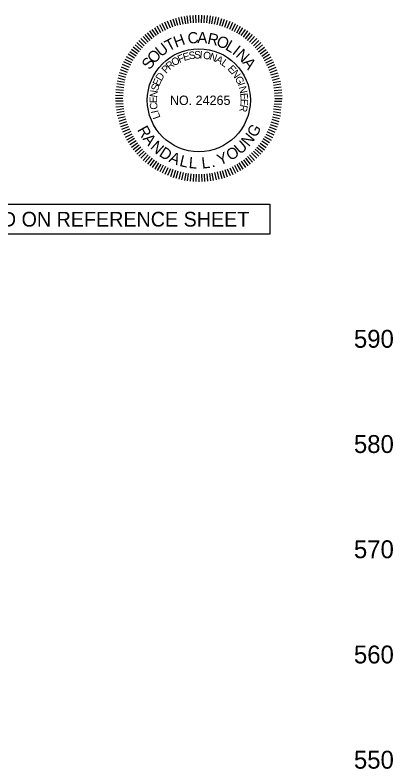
# Model space of a CAD drawing. Extents: x 1964849 to 1967422, y 1116563 to 1122211.
# Drawn here: x 1967242.5 to 1967421.9, y 1119125.5 to 1119483.7 of the extents above; entities that cross this region are included whole.
import ezdxf

# ---------------------------------------------------------------- set-up
doc = ezdxf.new("R2010")
doc.units = 0
for name, color, linetype in [('RD_DDB_Profile_Elev', 7, 'Continuous'), ('RD_Sketch1', 7, 'Continuous'), ('RD_TX_PEShield', 7, 'Continuous')]:
    doc.layers.add(name, color=color, linetype=linetype)

msp = doc.modelspace()

# ---------------------------------------------------------------- linework, layer by layer
at = {"layer": 'RD_Sketch1'}
msp.add_lwpolyline([(1967062.99, 1119393.87), (1967363.41, 1119393.87), (1967363.41, 1119379.61), (1967062.99, 1119379.61)], close=True, dxfattribs=at)
at = {"layer": 'RD_TX_PEShield'}
for p, q in [((1967316.27, 1119477.43), (1967314.93, 1119480.72)), ((1967316.27, 1119477.43), (1967314.93, 1119480.72)), ((1967317.44, 1119477.88), (1967316.22, 1119481.22)), ((1967317.44, 1119477.88), (1967316.22, 1119481.22)), ((1967318.61, 1119478.33), (1967317.51, 1119481.71)), ((1967318.61, 1119478.33), (1967317.51, 1119481.71)), ((1967319.83, 1119478.65), (1967318.85, 1119482.07)), ((1967319.83, 1119478.65), (1967318.85, 1119482.07)), ((1967321.04, 1119478.98), (1967320.18, 1119482.43)), ((1967321.04, 1119478.98), (1967320.18, 1119482.43)), ((1967322.26, 1119479.3), (1967321.52, 1119482.79)), ((1967322.26, 1119479.3), (1967321.52, 1119482.79)), ((1967323.5, 1119479.5), (1967322.88, 1119483)), ((1967323.5, 1119479.5), (1967322.88, 1119483)), ((1967324.74, 1119479.7), (1967324.25, 1119483.22)), ((1967324.74, 1119479.7), (1967324.25, 1119483.22)), ((1967325.98, 1119479.89), (1967325.61, 1119483.43)), ((1967325.98, 1119479.89), (1967325.61, 1119483.43)), ((1967327.24, 1119479.96), (1967326.99, 1119483.51)), ((1967327.24, 1119479.96), (1967326.99, 1119483.51)), ((1967328.5, 1119480.02), (1967328.37, 1119483.58)), ((1967328.5, 1119480.02), (1967328.37, 1119483.58)), ((1967329.75, 1119480.09), (1967329.75, 1119483.65)), ((1967329.75, 1119480.09), (1967329.75, 1119483.65)), ((1967331.01, 1119480.02), (1967331.13, 1119483.58)), ((1967331.01, 1119480.02), (1967331.13, 1119483.58)), ((1967332.26, 1119479.96), (1967332.51, 1119483.51)), ((1967332.26, 1119479.96), (1967332.51, 1119483.51)), ((1967333.52, 1119479.89), (1967333.89, 1119483.43)), ((1967333.52, 1119479.89), (1967333.89, 1119483.43)), ((1967334.76, 1119479.7), (1967335.26, 1119483.22)), ((1967334.76, 1119479.7), (1967335.26, 1119483.22)), ((1967336, 1119479.5), (1967336.62, 1119483)), ((1967336, 1119479.5), (1967336.62, 1119483)), ((1967337.25, 1119479.3), (1967337.99, 1119482.79)), ((1967337.25, 1119479.3), (1967337.99, 1119482.79)), ((1967337.25, 1119479.3), (1967337.99, 1119482.79)), ((1967338.46, 1119478.98), (1967339.32, 1119482.43)), ((1967338.46, 1119478.98), (1967339.32, 1119482.43)), ((1967338.46, 1119478.98), (1967339.32, 1119482.43)), ((1967339.68, 1119478.65), (1967340.66, 1119482.07)), ((1967339.68, 1119478.65), (1967340.66, 1119482.07)), ((1967339.68, 1119478.65), (1967340.66, 1119482.07)), ((1967340.89, 1119478.33), (1967341.99, 1119481.71)), ((1967340.89, 1119478.33), (1967341.99, 1119481.71)), ((1967340.89, 1119478.33), (1967341.99, 1119481.71)), ((1967342.07, 1119477.88), (1967343.28, 1119481.22)), ((1967342.07, 1119477.88), (1967343.28, 1119481.22)), ((1967342.07, 1119477.88), (1967343.28, 1119481.22)), ((1967343.24, 1119477.43), (1967344.57, 1119480.72)), ((1967343.24, 1119477.43), (1967344.57, 1119480.72)), ((1967343.24, 1119477.43), (1967344.57, 1119480.72)), ((1967310.67, 1119474.58), (1967308.79, 1119477.59)), ((1967310.67, 1119474.58), (1967308.79, 1119477.59)), ((1967311.73, 1119475.26), (1967309.95, 1119478.34)), ((1967311.73, 1119475.26), (1967309.95, 1119478.34)), ((1967312.85, 1119475.83), (1967311.18, 1119478.97)), ((1967312.85, 1119475.83), (1967311.18, 1119478.97)), ((1967313.97, 1119476.4), (1967312.41, 1119479.6)), ((1967313.97, 1119476.4), (1967312.41, 1119479.6)), ((1967315.09, 1119476.97), (1967313.64, 1119480.23)), ((1967315.09, 1119476.97), (1967313.64, 1119480.23)), ((1967344.41, 1119476.97), (1967345.86, 1119480.23)), ((1967344.41, 1119476.97), (1967345.86, 1119480.23)), ((1967344.41, 1119476.97), (1967345.86, 1119480.23)), ((1967345.53, 1119476.4), (1967347.09, 1119479.6)), ((1967345.53, 1119476.4), (1967347.09, 1119479.6)), ((1967345.53, 1119476.4), (1967347.09, 1119479.6)), ((1967346.65, 1119475.83), (1967348.32, 1119478.97)), ((1967346.65, 1119475.83), (1967348.32, 1119478.97)), ((1967346.65, 1119475.83), (1967348.32, 1119478.97)), ((1967347.78, 1119475.26), (1967349.56, 1119478.34)), ((1967347.78, 1119475.26), (1967349.56, 1119478.34)), ((1967347.78, 1119475.26), (1967349.56, 1119478.34)), ((1967348.83, 1119474.58), (1967350.71, 1119477.59)), ((1967348.83, 1119474.58), (1967350.71, 1119477.59)), ((1967348.83, 1119474.58), (1967350.71, 1119477.59)), ((1967305.63, 1119470.83), (1967303.25, 1119473.48)), ((1967305.63, 1119470.83), (1967303.25, 1119473.48)), ((1967306.61, 1119471.62), (1967304.33, 1119474.35)), ((1967306.61, 1119471.62), (1967304.33, 1119474.35)), ((1967307.59, 1119472.41), (1967305.4, 1119475.22)), ((1967307.59, 1119472.41), (1967305.4, 1119475.22)), ((1967308.57, 1119473.21), (1967306.47, 1119476.09)), ((1967308.57, 1119473.21), (1967306.47, 1119476.09)), ((1967309.62, 1119473.89), (1967307.63, 1119476.84)), ((1967309.62, 1119473.89), (1967307.63, 1119476.84)), ((1967349.88, 1119473.89), (1967351.87, 1119476.84)), ((1967349.88, 1119473.89), (1967351.87, 1119476.84)), ((1967349.88, 1119473.89), (1967351.87, 1119476.84)), ((1967350.94, 1119473.21), (1967353.03, 1119476.09)), ((1967350.94, 1119473.21), (1967353.03, 1119476.09)), ((1967350.94, 1119473.21), (1967353.03, 1119476.09)), ((1967351.92, 1119472.41), (1967354.11, 1119475.22)), ((1967351.92, 1119472.41), (1967354.11, 1119475.22)), ((1967351.92, 1119472.41), (1967354.11, 1119475.22)), ((1967352.89, 1119471.62), (1967355.18, 1119474.35)), ((1967352.89, 1119471.62), (1967355.18, 1119474.35)), ((1967352.89, 1119471.62), (1967355.18, 1119474.35)), ((1967353.87, 1119470.83), (1967356.25, 1119473.48)), ((1967353.87, 1119470.83), (1967356.25, 1119473.48)), ((1967353.87, 1119470.83), (1967356.25, 1119473.48)), ((1967302.97, 1119468.16), (1967300.32, 1119470.55)), ((1967302.97, 1119468.16), (1967300.32, 1119470.55)), ((1967303.86, 1119469.05), (1967301.3, 1119471.52)), ((1967303.86, 1119469.05), (1967301.3, 1119471.52)), ((1967304.74, 1119469.94), (1967302.27, 1119472.5)), ((1967304.74, 1119469.94), (1967302.27, 1119472.5)), ((1967354.76, 1119469.94), (1967357.23, 1119472.5)), ((1967354.76, 1119469.94), (1967357.23, 1119472.5)), ((1967354.76, 1119469.94), (1967357.23, 1119472.5)), ((1967355.65, 1119469.05), (1967358.21, 1119471.52)), ((1967355.65, 1119469.05), (1967358.21, 1119471.52)), ((1967355.65, 1119469.05), (1967358.21, 1119471.52)), ((1967356.54, 1119468.16), (1967359.18, 1119470.55)), ((1967356.54, 1119468.16), (1967359.18, 1119470.55)), ((1967356.54, 1119468.16), (1967359.18, 1119470.55)), ((1967299.91, 1119464.18), (1967296.96, 1119466.17)), ((1967299.91, 1119464.18), (1967296.96, 1119466.17)), ((1967300.59, 1119465.23), (1967297.71, 1119467.32)), ((1967300.59, 1119465.23), (1967297.71, 1119467.32)), ((1967301.38, 1119466.21), (1967298.58, 1119468.4)), ((1967301.38, 1119466.21), (1967298.58, 1119468.4)), ((1967302.17, 1119467.19), (1967299.45, 1119469.47)), ((1967302.17, 1119467.19), (1967299.45, 1119469.47)), ((1967357.33, 1119467.19), (1967360.05, 1119469.47)), ((1967357.33, 1119467.19), (1967360.05, 1119469.47)), ((1967357.33, 1119467.19), (1967360.05, 1119469.47)), ((1967358.12, 1119466.21), (1967360.92, 1119468.4)), ((1967358.12, 1119466.21), (1967360.92, 1119468.4)), ((1967358.12, 1119466.21), (1967360.92, 1119468.4)), ((1967358.91, 1119465.23), (1967361.79, 1119467.32)), ((1967358.91, 1119465.23), (1967361.79, 1119467.32)), ((1967358.91, 1119465.23), (1967361.79, 1119467.32)), ((1967359.6, 1119464.18), (1967362.55, 1119466.17)), ((1967359.6, 1119464.18), (1967362.55, 1119466.17)), ((1967359.6, 1119464.18), (1967362.55, 1119466.17)), ((1967297.97, 1119460.95), (1967294.83, 1119462.62)), ((1967297.97, 1119460.95), (1967294.83, 1119462.62)), ((1967298.54, 1119462.07), (1967295.45, 1119463.85)), ((1967298.54, 1119462.07), (1967295.45, 1119463.85)), ((1967299.22, 1119463.12), (1967296.21, 1119465.01)), ((1967299.22, 1119463.12), (1967296.21, 1119465.01)), ((1967360.28, 1119463.12), (1967363.3, 1119465.01)), ((1967360.28, 1119463.12), (1967363.3, 1119465.01)), ((1967360.28, 1119463.12), (1967363.3, 1119465.01)), ((1967360.97, 1119462.07), (1967364.05, 1119463.85)), ((1967360.97, 1119462.07), (1967364.05, 1119463.85)), ((1967360.97, 1119462.07), (1967364.05, 1119463.85)), ((1967361.54, 1119460.95), (1967364.68, 1119462.62)), ((1967361.54, 1119460.95), (1967364.68, 1119462.62)), ((1967361.54, 1119460.95), (1967364.68, 1119462.62)), ((1967296.82, 1119458.71), (1967293.57, 1119460.15)), ((1967296.82, 1119458.71), (1967293.57, 1119460.15)), ((1967297.4, 1119459.83), (1967294.2, 1119461.39)), ((1967297.4, 1119459.83), (1967294.2, 1119461.39)), ((1967362.11, 1119459.83), (1967365.31, 1119461.39)), ((1967362.11, 1119459.83), (1967365.31, 1119461.39)), ((1967362.11, 1119459.83), (1967365.31, 1119461.39)), ((1967362.68, 1119458.71), (1967365.93, 1119460.15)), ((1967362.68, 1119458.71), (1967365.93, 1119460.15)), ((1967362.68, 1119458.71), (1967365.93, 1119460.15)), ((1967295.47, 1119455.18), (1967292.09, 1119456.28)), ((1967295.47, 1119455.18), (1967292.09, 1119456.28)), ((1967295.92, 1119456.36), (1967292.58, 1119457.57)), ((1967295.92, 1119456.36), (1967292.58, 1119457.57)), ((1967296.37, 1119457.53), (1967293.08, 1119458.86)), ((1967296.37, 1119457.53), (1967293.08, 1119458.86)), ((1967363.13, 1119457.53), (1967366.43, 1119458.86)), ((1967363.13, 1119457.53), (1967366.43, 1119458.86)), ((1967363.13, 1119457.53), (1967366.43, 1119458.86)), ((1967363.58, 1119456.36), (1967366.92, 1119457.57)), ((1967363.58, 1119456.36), (1967366.92, 1119457.57)), ((1967363.58, 1119456.36), (1967366.92, 1119457.57)), ((1967364.03, 1119455.18), (1967367.42, 1119456.28)), ((1967364.03, 1119455.18), (1967367.42, 1119456.28)), ((1967364.03, 1119455.18), (1967367.42, 1119456.28)), ((1967294.5, 1119451.54), (1967291.01, 1119452.28)), ((1967294.5, 1119451.54), (1967291.01, 1119452.28)), ((1967294.82, 1119452.76), (1967291.37, 1119453.62)), ((1967294.82, 1119452.76), (1967291.37, 1119453.62)), ((1967295.15, 1119453.97), (1967291.73, 1119454.95)), ((1967295.15, 1119453.97), (1967291.73, 1119454.95)), ((1967364.36, 1119453.97), (1967367.78, 1119454.95)), ((1967364.36, 1119453.97), (1967367.78, 1119454.95)), ((1967364.36, 1119453.97), (1967367.78, 1119454.95)), ((1967364.68, 1119452.76), (1967368.13, 1119453.62)), ((1967364.68, 1119452.76), (1967368.13, 1119453.62)), ((1967364.68, 1119452.76), (1967368.13, 1119453.62)), ((1967365.01, 1119451.54), (1967368.49, 1119452.28)), ((1967365.01, 1119451.54), (1967368.49, 1119452.28)), ((1967365.01, 1119451.54), (1967368.49, 1119452.28)), ((1967294.1, 1119449.06), (1967290.58, 1119449.55)), ((1967294.1, 1119449.06), (1967290.58, 1119449.55)), ((1967294.3, 1119450.3), (1967290.8, 1119450.91)), ((1967294.3, 1119450.3), (1967290.8, 1119450.91)), ((1967365.21, 1119450.3), (1967368.71, 1119450.91)), ((1967365.21, 1119450.3), (1967368.71, 1119450.91)), ((1967365.21, 1119450.3), (1967368.71, 1119450.91)), ((1967365.4, 1119449.06), (1967368.92, 1119449.55)), ((1967365.4, 1119449.06), (1967368.92, 1119449.55)), ((1967365.4, 1119449.06), (1967368.92, 1119449.55)), ((1967293.77, 1119445.3), (1967290.22, 1119445.43)), ((1967293.77, 1119445.3), (1967290.22, 1119445.43)), ((1967293.84, 1119446.56), (1967290.29, 1119446.8)), ((1967293.84, 1119446.56), (1967290.29, 1119446.8)), ((1967293.91, 1119447.81), (1967290.36, 1119448.19)), ((1967293.91, 1119447.81), (1967290.36, 1119448.19)), ((1967365.6, 1119447.81), (1967369.14, 1119448.19)), ((1967365.6, 1119447.81), (1967369.14, 1119448.19)), ((1967365.6, 1119447.81), (1967369.14, 1119448.19)), ((1967365.67, 1119446.56), (1967369.21, 1119446.8)), ((1967365.67, 1119446.56), (1967369.21, 1119446.8)), ((1967365.67, 1119446.56), (1967369.21, 1119446.8)), ((1967365.73, 1119445.3), (1967369.29, 1119445.43)), ((1967365.73, 1119445.3), (1967369.29, 1119445.43)), ((1967365.73, 1119445.3), (1967369.29, 1119445.43)), ((1967293.71, 1119444.05), (1967290.15, 1119444.05)), ((1967293.71, 1119444.05), (1967290.15, 1119444.05)), ((1967293.77, 1119442.79), (1967290.22, 1119442.67)), ((1967293.77, 1119442.79), (1967290.22, 1119442.67)), ((1967293.84, 1119441.53), (1967290.29, 1119441.29)), ((1967293.84, 1119441.53), (1967290.29, 1119441.29)), ((1967365.53, 1119441.54), (1967369.07, 1119441.3)), ((1967365.53, 1119441.54), (1967369.07, 1119441.3)), ((1967365.67, 1119442.79), (1967369.21, 1119442.67)), ((1967365.67, 1119442.79), (1967369.21, 1119442.67)), ((1967365.8, 1119444.05), (1967369.36, 1119444.05)), ((1967365.8, 1119444.05), (1967369.36, 1119444.05)), ((1967365.8, 1119444.05), (1967369.36, 1119444.05)), ((1967293.91, 1119440.28), (1967290.36, 1119439.91)), ((1967293.91, 1119440.28), (1967290.36, 1119439.91)), ((1967294.1, 1119439.04), (1967290.58, 1119438.54)), ((1967294.1, 1119439.04), (1967290.58, 1119438.54)), ((1967294.3, 1119437.79), (1967290.8, 1119437.18)), ((1967294.3, 1119437.79), (1967290.8, 1119437.18)), ((1967365.14, 1119437.81), (1967368.64, 1119437.19)), ((1967365.14, 1119437.81), (1967368.64, 1119437.19)), ((1967365.27, 1119439.05), (1967368.78, 1119438.56)), ((1967365.27, 1119439.05), (1967368.78, 1119438.56)), ((1967365.4, 1119440.3), (1967368.92, 1119439.93)), ((1967365.4, 1119440.3), (1967368.92, 1119439.93)), ((1967294.5, 1119436.55), (1967291.01, 1119435.81)), ((1967294.5, 1119436.55), (1967291.01, 1119435.81)), ((1967294.82, 1119435.34), (1967291.37, 1119434.48)), ((1967294.82, 1119435.34), (1967291.37, 1119434.48)), ((1967295.15, 1119434.12), (1967291.73, 1119433.14)), ((1967295.15, 1119434.12), (1967291.73, 1119433.14)), ((1967364.36, 1119434.12), (1967367.78, 1119433.14)), ((1967364.36, 1119434.12), (1967367.78, 1119433.14)), ((1967364.68, 1119435.34), (1967368.13, 1119434.48)), ((1967364.68, 1119435.34), (1967368.13, 1119434.48)), ((1967365.01, 1119436.55), (1967368.49, 1119435.81)), ((1967365.01, 1119436.55), (1967368.49, 1119435.81)), ((1967295.47, 1119432.91), (1967292.09, 1119431.81)), ((1967295.92, 1119431.73), (1967292.58, 1119430.52)), ((1967295.92, 1119431.73), (1967292.58, 1119430.52)), ((1967296.37, 1119430.56), (1967293.08, 1119429.23)), ((1967296.37, 1119430.56), (1967293.08, 1119429.23)), ((1967363.13, 1119430.56), (1967366.43, 1119429.23)), ((1967363.13, 1119430.56), (1967366.43, 1119429.23)), ((1967363.58, 1119431.73), (1967366.92, 1119430.52)), ((1967363.58, 1119431.73), (1967366.92, 1119430.52)), ((1967364.03, 1119432.91), (1967367.42, 1119431.81)), ((1967364.03, 1119432.91), (1967367.42, 1119431.81)), ((1967296.82, 1119429.38), (1967293.57, 1119427.94)), ((1967296.82, 1119429.38), (1967293.57, 1119427.94)), ((1967297.4, 1119428.26), (1967294.2, 1119426.71)), ((1967297.4, 1119428.26), (1967294.2, 1119426.71)), ((1967297.97, 1119427.14), (1967294.83, 1119425.47)), ((1967297.97, 1119427.14), (1967294.83, 1119425.47)), ((1967361.54, 1119427.14), (1967364.68, 1119425.47)), ((1967361.54, 1119427.14), (1967364.68, 1119425.47)), ((1967362.11, 1119428.26), (1967365.31, 1119426.71)), ((1967362.11, 1119428.26), (1967365.31, 1119426.71)), ((1967362.68, 1119429.38), (1967365.93, 1119427.94)), ((1967362.68, 1119429.38), (1967365.93, 1119427.94)), ((1967298.54, 1119426.02), (1967295.45, 1119424.24)), ((1967298.54, 1119426.02), (1967295.45, 1119424.24)), ((1967299.22, 1119424.97), (1967296.21, 1119423.08)), ((1967299.22, 1119424.97), (1967296.21, 1119423.08)), ((1967299.91, 1119423.91), (1967296.96, 1119421.93)), ((1967299.91, 1119423.91), (1967296.96, 1119421.93)), ((1967359.6, 1119423.91), (1967362.55, 1119421.93)), ((1967359.6, 1119423.91), (1967362.55, 1119421.93)), ((1967360.28, 1119424.97), (1967363.3, 1119423.08)), ((1967360.28, 1119424.97), (1967363.3, 1119423.08)), ((1967360.97, 1119426.02), (1967364.05, 1119424.24)), ((1967360.97, 1119426.02), (1967364.05, 1119424.24)), ((1967300.59, 1119422.86), (1967297.71, 1119420.77)), ((1967300.59, 1119422.86), (1967297.71, 1119420.77)), ((1967301.38, 1119421.88), (1967298.58, 1119419.69)), ((1967301.38, 1119421.88), (1967298.58, 1119419.69)), ((1967302.17, 1119420.9), (1967299.45, 1119418.62)), ((1967302.17, 1119420.9), (1967299.45, 1119418.62)), ((1967302.97, 1119419.93), (1967300.32, 1119417.54)), ((1967302.97, 1119419.93), (1967300.32, 1119417.54)), ((1967356.54, 1119419.93), (1967359.18, 1119417.54)), ((1967356.54, 1119419.93), (1967359.18, 1119417.54)), ((1967357.33, 1119420.9), (1967360.05, 1119418.62)), ((1967357.33, 1119420.9), (1967360.05, 1119418.62)), ((1967358.12, 1119421.88), (1967360.92, 1119419.69)), ((1967358.12, 1119421.88), (1967360.92, 1119419.69)), ((1967358.91, 1119422.86), (1967361.79, 1119420.77)), ((1967358.91, 1119422.86), (1967361.79, 1119420.77)), ((1967303.86, 1119419.04), (1967301.3, 1119416.57)), ((1967303.86, 1119419.04), (1967301.3, 1119416.57)), ((1967304.74, 1119418.15), (1967302.27, 1119415.59)), ((1967304.74, 1119418.15), (1967302.27, 1119415.59)), ((1967305.63, 1119417.26), (1967303.25, 1119414.61)), ((1967305.63, 1119417.26), (1967303.25, 1119414.61)), ((1967306.61, 1119416.47), (1967304.33, 1119413.74)), ((1967306.61, 1119416.47), (1967304.33, 1119413.74)), ((1967352.89, 1119416.47), (1967355.18, 1119413.74)), ((1967352.89, 1119416.47), (1967355.18, 1119413.74)), ((1967353.87, 1119417.26), (1967356.25, 1119414.61)), ((1967354.76, 1119418.15), (1967357.23, 1119415.59)), ((1967354.76, 1119418.15), (1967357.23, 1119415.59)), ((1967355.65, 1119419.04), (1967358.21, 1119416.57)), ((1967355.65, 1119419.04), (1967358.21, 1119416.57)), ((1967307.59, 1119415.68), (1967305.4, 1119412.87)), ((1967307.59, 1119415.68), (1967305.4, 1119412.87)), ((1967308.57, 1119414.88), (1967306.47, 1119412)), ((1967308.57, 1119414.88), (1967306.47, 1119412)), ((1967309.62, 1119414.2), (1967307.63, 1119411.25)), ((1967309.62, 1119414.2), (1967307.63, 1119411.25)), ((1967310.67, 1119413.51), (1967308.79, 1119410.5)), ((1967310.67, 1119413.51), (1967308.79, 1119410.5)), ((1967311.73, 1119412.83), (1967309.95, 1119409.75)), ((1967311.73, 1119412.83), (1967309.95, 1119409.75)), ((1967347.78, 1119412.83), (1967349.56, 1119409.75)), ((1967347.78, 1119412.83), (1967349.56, 1119409.75)), ((1967348.83, 1119413.51), (1967350.71, 1119410.5)), ((1967348.83, 1119413.51), (1967350.71, 1119410.5)), ((1967349.88, 1119414.2), (1967351.87, 1119411.25)), ((1967349.88, 1119414.2), (1967351.87, 1119411.25)), ((1967350.94, 1119414.88), (1967353.03, 1119412)), ((1967350.94, 1119414.88), (1967353.03, 1119412)), ((1967351.92, 1119415.68), (1967354.11, 1119412.87)), ((1967351.92, 1119415.68), (1967354.11, 1119412.87)), ((1967312.85, 1119412.26), (1967311.18, 1119409.12)), ((1967312.85, 1119412.26), (1967311.18, 1119409.12)), ((1967313.97, 1119411.69), (1967312.41, 1119408.49)), ((1967313.97, 1119411.69), (1967312.41, 1119408.49)), ((1967315.09, 1119411.12), (1967313.64, 1119407.86)), ((1967315.09, 1119411.12), (1967313.64, 1119407.86)), ((1967316.27, 1119410.67), (1967314.93, 1119407.37)), ((1967316.27, 1119410.67), (1967314.93, 1119407.37)), ((1967317.44, 1119410.22), (1967316.22, 1119406.87)), ((1967317.44, 1119410.22), (1967316.22, 1119406.87)), ((1967318.61, 1119409.76), (1967317.51, 1119406.38)), ((1967318.61, 1119409.76), (1967317.51, 1119406.38)), ((1967319.83, 1119409.44), (1967318.85, 1119406.02)), ((1967319.83, 1119409.44), (1967318.85, 1119406.02)), ((1967321.04, 1119409.11), (1967320.18, 1119405.66)), ((1967321.04, 1119409.11), (1967320.18, 1119405.66)), ((1967338.46, 1119409.11), (1967339.32, 1119405.66)), ((1967338.46, 1119409.11), (1967339.32, 1119405.66)), ((1967339.68, 1119409.44), (1967340.66, 1119406.02)), ((1967339.68, 1119409.44), (1967340.66, 1119406.02)), ((1967340.89, 1119409.76), (1967341.99, 1119406.38)), ((1967340.89, 1119409.76), (1967341.99, 1119406.38)), ((1967342.07, 1119410.22), (1967343.28, 1119406.87)), ((1967342.07, 1119410.22), (1967343.28, 1119406.87)), ((1967343.24, 1119410.67), (1967344.57, 1119407.37)), ((1967343.24, 1119410.67), (1967344.57, 1119407.37)), ((1967344.41, 1119411.12), (1967345.86, 1119407.86)), ((1967344.41, 1119411.12), (1967345.86, 1119407.86)), ((1967345.53, 1119411.69), (1967347.09, 1119408.49)), ((1967345.53, 1119411.69), (1967347.09, 1119408.49)), ((1967346.65, 1119412.26), (1967348.32, 1119409.12)), ((1967346.65, 1119412.26), (1967348.32, 1119409.12)), ((1967322.26, 1119408.79), (1967321.52, 1119405.31)), ((1967322.26, 1119408.79), (1967321.52, 1119405.31)), ((1967323.5, 1119408.59), (1967322.88, 1119405.09)), ((1967323.5, 1119408.59), (1967322.88, 1119405.09)), ((1967324.74, 1119408.39), (1967324.25, 1119404.87)), ((1967324.74, 1119408.39), (1967324.25, 1119404.87)), ((1967325.98, 1119408.2), (1967325.61, 1119404.66)), ((1967325.98, 1119408.2), (1967325.61, 1119404.66)), ((1967327.24, 1119408.13), (1967326.99, 1119404.59)), ((1967327.24, 1119408.13), (1967326.99, 1119404.59)), ((1967328.5, 1119408.07), (1967328.37, 1119404.51)), ((1967328.5, 1119408.07), (1967328.37, 1119404.51)), ((1967329.75, 1119408), (1967329.75, 1119404.44)), ((1967329.75, 1119408), (1967329.75, 1119404.44)), ((1967331.01, 1119408.07), (1967331.13, 1119404.51)), ((1967331.01, 1119408.07), (1967331.13, 1119404.51)), ((1967332.26, 1119408.13), (1967332.51, 1119404.59)), ((1967332.26, 1119408.13), (1967332.51, 1119404.59)), ((1967333.52, 1119408.2), (1967333.89, 1119404.66)), ((1967333.52, 1119408.2), (1967333.89, 1119404.66)), ((1967334.76, 1119408.39), (1967335.26, 1119404.87)), ((1967334.76, 1119408.39), (1967335.26, 1119404.87)), ((1967336, 1119408.59), (1967336.62, 1119405.09)), ((1967336, 1119408.59), (1967336.62, 1119405.09)), ((1967337.25, 1119408.79), (1967337.99, 1119405.31)), ((1967337.25, 1119408.79), (1967337.99, 1119405.31))]:
    msp.add_line(p, q, dxfattribs=at)
msp.add_circle((1967329.75, 1119443.17), 24.48, dxfattribs=at)

# ---------------------------------------------------------------- texts
at = {"layer": 'RD_DDB_Profile_Elev'}
for s, p in [('590', (1967403.42, 1119325.58)), ('580', (1967403.42, 1119275.58)), ('570', (1967403.42, 1119225.58)), ('560', (1967403.42, 1119175.58)), ('550', (1967403.42, 1119125.58))]:
    msp.add_text(s, height=8.5, dxfattribs=at).set_placement(p)
at = {"layer": 'RD_Sketch1'}
msp.add_text('ALIGNMENT CONTROL CAN BE FOUND ON REFERENCE SHEET', height=7, dxfattribs=at).set_placement((1967066.64, 1119383.16))
at = {"layer": 'RD_TX_PEShield'}
for s, height, rotation, p in [('H', 5.34, 19.9102, (1967318.85, 1119468.09)), ('C', 5.34, 6.8832, (1967324.75, 1119469.91)), ('A', 5.34, 357.9448, (1967328.96, 1119470.36)), ('R', 5.34, 348.267, (1967333.54, 1119470.1)), ('O', 5.34, 339.3286, (1967337.68, 1119469.19)), ('U', 5.34, 37.7726, (1967311.73, 1119463.54)), ('T', 5.34, 28.0947, (1967315.41, 1119466.28)), ('L', 5.34, 329.6507, (1967341.94, 1119467.48)), ('O', 5.34, 47.4504, (1967308.56, 1119460.22)), ('S', 3.56, 8.6909, (1967325.24, 1119462.56)), ('S', 3.56, 1.79, (1967327.6, 1119462.96)), ('I', 3.56, 354.889, (1967330, 1119463.07)), ('O', 3.56, 350.4045, (1967331.55, 1119462.99)), ('I', 5.34, 321.4663, (1967345.28, 1119465.5)), ('N', 5.34, 317.0007, (1967346.97, 1119464.22)), ('S', 5.34, 54.9027, (1967306.53, 1119457.33)), ('O', 3.56, 31.7869, (1967318, 1119459.23)), ('F', 3.56, 23.0853, (1967320.56, 1119460.83)), ('E', 3.56, 16.1843, (1967322.75, 1119461.8)), ('N', 3.56, 341.7029, (1967334.53, 1119462.49)), ('A', 3.56, 333.0013, (1967337.4, 1119461.55)), ('L', 3.56, 324.2997, (1967340.09, 1119460.18)), ('A', 5.34, 307.3229, (1967350.27, 1119461.03)), ('P', 3.56, 46.7912, (1967314.24, 1119455.64)), ('R', 3.56, 39.8902, (1967315.85, 1119457.41)), ('E', 3.56, 313.2251, (1967343.17, 1119457.88)), ('D', 3.56, 59.074, (1967311.94, 1119452.05)), ('N', 3.56, 305.7317, (1967344.97, 1119456)), ('E', 3.56, 66.5674, (1967310.93, 1119449.66)), ('G', 3.56, 297.0301, (1967346.74, 1119453.55)), ('S', 3.56, 73.4683, (1967310.29, 1119447.35)), ('I', 3.56, 288.3285, (1967348.11, 1119450.86)), ('N', 3.56, 283.8441, (1967348.66, 1119449.4)), ('E', 3.56, 89.6633, (1967309.9, 1119441.75)), ('N', 3.56, 82.17, (1967309.88, 1119444.35)), ('E', 3.56, 275.1424, (1967349.38, 1119446.47)), ('C', 3.56, 97.7667, (1967310.29, 1119438.97)), ('E', 3.56, 267.6491, (1967349.65, 1119443.88)), ('I', 3.56, 102.2511, (1967310.68, 1119437.46)), ('R', 3.56, 260.1557, (1967349.57, 1119441.28)), ('L', 3.56, 109.7445, (1967311.59, 1119435.02)), ('R', 5.34, 299.1493, (1967300.35, 1119429.19)), ('G', 5.34, 60.1113, (1967356.86, 1119425.14)), ('N', 5.34, 50.4335, (1967353.45, 1119420.84)), ('A', 5.34, 308.0877, (1967302.88, 1119424.8)), ('N', 5.34, 317.7655, (1967306.35, 1119420.54)), ('U', 5.34, 40.7556, (1967349.36, 1119417.18)), ('D', 5.34, 327.4433, (1967310.49, 1119416.93)), ('O', 5.34, 31.0778, (1967344.71, 1119414.25)), ('A', 5.34, 337.1212, (1967315.17, 1119414.06)), ('L', 5.34, 346.799, (1967320.27, 1119412.02)), ('L', 5.34, 354.9835, (1967324.8, 1119410.99)), ('L', 5.34, 6.5171, (1967331.34, 1119410.65)), ('Y', 5.34, 21.4, (1967339.63, 1119412.15)), ('.', 5.34, 14.7016, (1967335.95, 1119411.21))]:
    msp.add_text(s, height=height, rotation=rotation, dxfattribs=at).set_placement(p)
msp.add_text('NO. 24265', height=4.45, dxfattribs=at).set_placement((1967316, 1119440.94))

doc.saveas('drawing.dxf')
